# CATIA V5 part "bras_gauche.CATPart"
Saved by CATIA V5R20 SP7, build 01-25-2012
Part number: bras_gauche
Bounding box of the stored display mesh (mm): x -584.177 to 29.979, y -420 to 730.489, z 0 to 20
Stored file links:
  U:\IAO\thinkmotion catia2\bras_gauche.CATPart
  U:\IAO\thinkmotion catia2\Ass_862_adubourgno.CATProduct
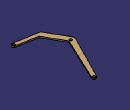
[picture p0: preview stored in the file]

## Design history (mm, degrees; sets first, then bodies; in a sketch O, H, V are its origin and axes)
Set1
  Plane1: linked copy from another document
  Point1 "C": linked copy from another document
  Point2 "A": linked copy from another document
  Point3 "J": linked copy from another document
  Point4 "I": linked copy from another document
  Point5 "N": linked copy from another document
  Point6 "E": linked copy from another document
Body1 (main body)
  Sketch1 on Plane1, origin (0, 0, 0), H (1, 0, 0), V (0, 1, 0)
    circle A1 centre (0, -390) radius 20
    point P1 (0, -390)
    reference projected point E1 (0, -390) from Point1
    construction line L1 (0, 700) -> (0, -390)
    point P2 (0, 700)
    point P3 (0, -390)
    reference projected point E2 (0, -390) from Point1
    reference projected point E3 (0, 700) from Point2
    line L2 (-10.2606, -418.1908) -> (-390.8059, -351.0904)
    point P4 (0, -420)
    reference projected point E4 (0, -390) from Point1
    line L3 (14.298, -363.6264) -> (-318.128, -305.0107)
    arc A2 centre (0, -390) radius 30 from (-10.2606, -418.1908) to (14.298, -363.6264) ccw
    point P5 (0, -390)
    reference projected point E5 (0, -390) from Point1
    construction line L4 (-350, 0) -> (-524.226, 0)
    point P8 (-350, 0)
    point P9 (-524.226, 0)
    reference projected point E6 (-524.226, 0) from Point4
    reference projected point E7 (-350, 0) from Point5
    construction line L5 (-549.1609, 14.3962) -> (-524.226, 0)
    point P10 (-549.1609, 14.3962)
    point P11 (-524.226, 0)
    reference projected point E8 (-524.226, 0) from Point4
    point P12 (-524.226, 0)
    point P13 (-549.1609, -14.3962)
    construction line L6 (-549.1609, -14.3962) -> (-524.226, 0)
    arc A3 centre (-524.226, 0) radius 60 from (-576.1875, 30) to (-576.1875, -30) ccw
    point P14 (-524.226, 0)
    point P15 (-576.1875, -30)
    point P16 (-576.1875, 30)
    reference projected point E9 (-524.226, 0) from Point4
    circle A4 centre (-524.226, 0) radius 20
    point P17 (-524.226, 0)
    reference projected point E10 (-524.226, 0) from Point4
    line L7 (-576.1875, -30) -> (-390.8059, -351.0904)
    line L8 (-494.226, 0) -> (-318.128, -305.0107)
    point P18 (-494.226, 0)
    reference projected point E11 (-524.226, 0) from Point4
    line L9 (-576.1875, 30) -> (-224.1326, 718.6512)
    point P21 (-227.2218, 712.6086)
    construction line L10 (-200, 700) -> (-524.226, 0)
    point P22 (-200, 700)
    point P23 (-524.226, 0)
    reference projected point E12 (-200, 700) from Point6
    reference projected point E13 (-524.226, 0) from Point4
    axis line L11 (-200, 700) -> (-164.0462, 683.3469)
    point P24 (-200, 700)
    reference projected point E14 (-200, 700) from Point6
    reference projected point E15 (-200, 700) from Point6
    line L12 (-494.226, 0) -> (-175.1551, 682.3088)
    point P26 (-172.7782, 687.3914)
    reference projected point E16 (-200, 700) from Point6
    arc A5 centre (-200, 700) radius 30.5 from (-175.1551, 682.3088) to (-224.1326, 718.6512) ccw
    point P27 (-200, 700)
    reference projected point E17 (-200, 700) from Point6
    circle A6 centre (-200, 700) radius 20
    point P30 (-200, 700)
    reference projected point E18 (-200, 700) from Point6
    radius A1 = 20
    distance E1 P1 = 0
    distance E2 P3 = 0
    distance E3 P2 = 0
    distance E4 P4 = 30
    angle L2 L1 = 80
    distance L2 L3 = 58
    radius A2 = 30
    distance E5 P5 = 0
    distance E6 P9 = 0
    distance E7 P8 = 0
    distance E8 P11 = 0
    angle L4 L5 = 150
    distance E9 P14 = 0
    radius A3 = 60
    radius A4 = 20
    distance E10 P17 = 0
    angle L6 L7 = 90
    distance E11 P18 = 30
    distance E12 P22 = 0
    distance E13 P23 = 0
    distance E14 P24 = 0
    angle L10 L11 = 90
    distance L11 P21 = 0
    distance E15 P21 = 30
    distance L11 P26 = 0
    distance E16 P26 = 30
    radius A5 = 30.5
    distance E17 P27 = 0
    radius A6 = 20
    distance E18 P30 = 0
    coincidence: P4 V, P4 L2, P15 L6, P16 L5, P18 L4, P21 L9, P26 L12
    symmetry: P11 P12 L4, P10 P13 L4, L5 L6 L4
    parallelism: L8 L7
  Pad1: profile Sketch1, direction (0, 0, 1), length 20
